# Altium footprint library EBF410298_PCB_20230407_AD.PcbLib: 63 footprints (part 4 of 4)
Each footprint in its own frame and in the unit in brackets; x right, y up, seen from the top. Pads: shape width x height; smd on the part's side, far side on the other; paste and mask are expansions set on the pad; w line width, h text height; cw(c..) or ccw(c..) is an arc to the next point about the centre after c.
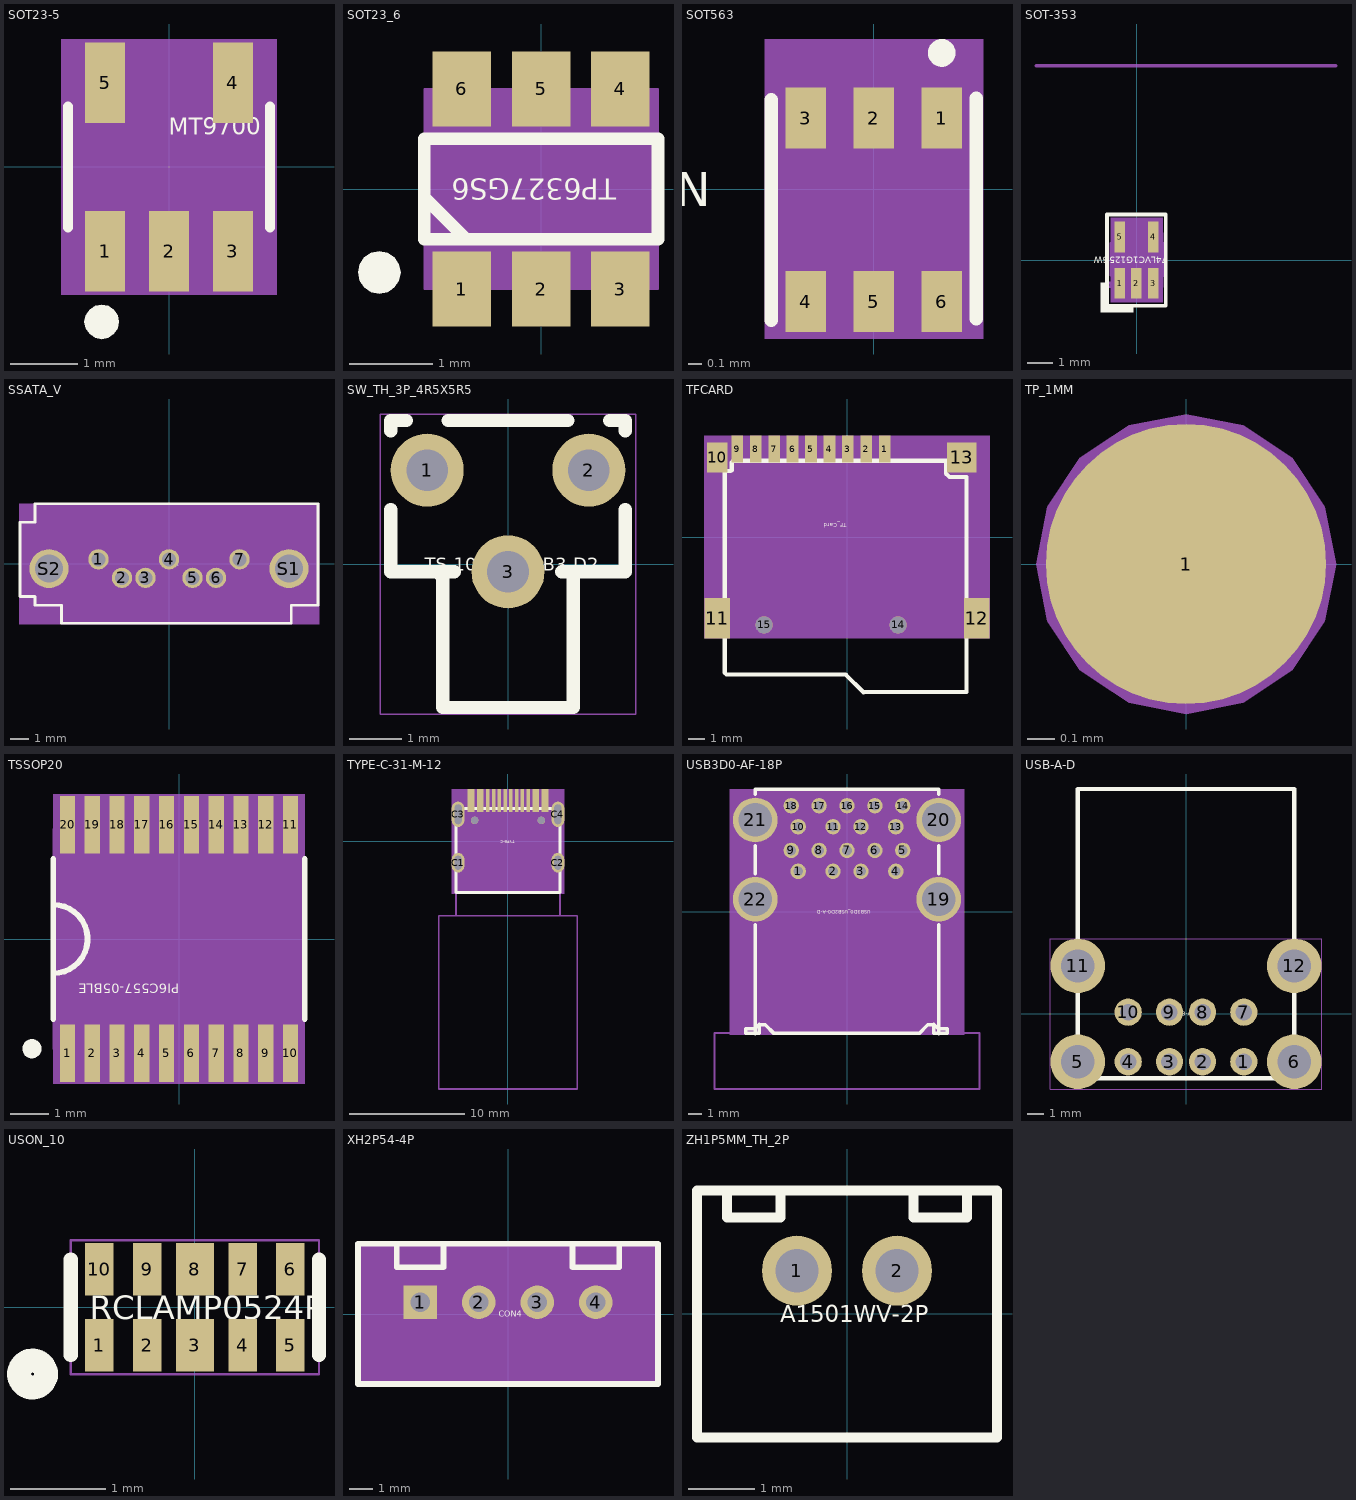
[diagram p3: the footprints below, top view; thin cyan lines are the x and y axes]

## SOT23-5 [mm] "SOT23-5"
pads (5):
  rect 0.599x1.199 smd: 1(-0.95,-1.25) 2(0,-1.25) 3(0.95,-1.25) 4(0.95,1.25) 5(-0.95,1.25)
Top Overlay:
  dashed: -1,-2.555 -0.902,-2.535 -0.82,-2.48 -0.765,-2.398 -0.745,-2.3 -0.765,-2.202 -0.783,-2.175 -0.82,-2.12 -0.902,-2.065 -1,-2.045 -1.098,-2.065 -1.18,-2.12 -1.217,-2.175 -1.235,-2.202 -1.255,-2.3 -1.235,-2.398 -1.18,-2.48 -1.098,-2.535
  lines w0.15: -1.5,-0.9 -1.5,0.9 ; 1.5,-0.9 1.5,0.9
  text "MT9700" at 0,0.475 h0.25
Top 3D Body:
  region: -1.6,1.9 -1.6,-1.9 1.6,-1.9 1.6,1.9
Mechanical 17:
  text "2" at 0,-1.21 h0.1
  text "1" at -0.95,-1.21 h0.1
  text "3" at 0.95,-1.21 h0.1
  text "4" at 0.95,1.29 h0.1
  text "5" at -0.95,1.29 h0.1
Top Assembly:
  lines w0.15: -1.5,-0.85 1.5,-0.85 1.5,0.85 -1.5,0.85 -1.5,-0.85
3D body: height 3.81, standoff 0, extent -1.6,-1.9 1.6,1.9

## SOT23_6 [mm] "SOT23_6"
pads (6):
  rect 0.7x0.9 smd: 1(-0.95,-1.2) 2(0,-1.2) 3(0.95,-1.2) 4(0.95,1.2) 5(0,1.2) 6(-0.95,1.2)
Top Overlay:
  dashed: -2.195,-1 -2.176,-1.098 -2.12,-1.18 -2.038,-1.236 -1.94,-1.255 -1.842,-1.236 -1.815,-1.217 -1.76,-1.18 -1.704,-1.098 -1.685,-1 -1.704,-0.902 -1.76,-0.82 -1.815,-0.783 -1.842,-0.764 -1.94,-0.745 -2.038,-0.764 -2.12,-0.82 -2.176,-0.902
  lines w0.15: -1.4,-0.1 -0.9,-0.6 ; -1.4,-0.6 -1.4,0.6 1.4,0.6 1.4,-0.6 -1.4,-0.6
  text "TP6327GS6" at 0.9,0.125 h0.25
Top 3D Body:
  region: -1.4,-1.2 1.4,-1.2 1.4,1.2 -1.4,1.2
Mechanical 17:
  text "1" at -0.696,-1.2 h0.64
  text "5" at 0.254,1.2 h0.64
  text "4" at 1.204,1.2 h0.64
  text "2" at 0.254,-1.2 h0.64
  text "6" at -0.696,1.2 h0.64
  text "3" at 1.204,-1.2 h0.64
Top Assembly:
  lines w0.025: -1.4,-1.2 1.4,-1.2 1.4,1.2 -1.4,1.2 -1.4,-1.2
3D body: height 3.81, standoff 0, extent -1.4,-1.2 1.4,1.2

## SOT563 [mm] "SOT563"
pads (6):
  rect 0.3x0.45 smd: 1(0.499,0.521) 2(-0.001,0.521) 3(-0.501,0.521) 4(-0.501,-0.829) 5(-0.001,-0.829) 6(0.499,-0.829)
Top Overlay:
  circle w0.1: c0.499,1.001 r0.052
  lines w0.1: -0.754,-0.966 -0.754,0.657 ; 0.754,-0.955 0.754,0.668
  text "NUP5120X6T1G" at -1.2,0.125 h0.25
Top 3D Body:
  region: 0.804,1.104 0.804,-1.104 -0.804,-1.104 -0.804,1.104
Mechanical 17:
  text "2" at -0.245,0.521 h0.3
  text "4" at -0.745,-0.829 h0.3
  text "6" at 0.255,-0.829 h0.3
  text "5" at -0.245,-0.829 h0.3
  text "1" at 0.255,0.521 h0.3
  text "3" at -0.745,0.521 h0.3
3D body: height 3.81, standoff 0, extent -0.804,-1.104 0.804,1.104

## SOT-353 [mil] "SOT-353"
pads (5):
  rect 16x47 smd: 1(-25.91,-35.43) 2(-0.32,-35.43) 3(25.28,-35.43) 4(25.28,35.43) 5(-25.91,35.43)
Top Overlay:
  dashed: -45.31,-35 -55.31,-35 -55.31,-80 -5.32,-80 -5.32,-70 -45.31,-70
  lines w6: -45.31,-70 44.69,-70 44.69,70 -45.31,70 -45.31,-70
  text "74LVC1G125GW" at 47.23,4.92 h9.84
Mechanical 5:
  dashed: -39.69,-65 39.69,-65 39.69,65 -39.69,65
Top 3D Body:
  region: -39.69,-65 39.69,-65 39.69,65 -39.69,65
Top Component Center:
  circle w1: c-0.32,0 r11.81
  circle w1: c-0.32,0 r11.81
  lines w1: -16.06,0 15.43,0 -16.06,0 ; -0.32,-15.75 -0.32,15.75 -0.32,-15.75
Mechanical 17:
  text "5" at -19.11,35.43 h17
  text "1" at -19.11,-35.43 h17
  text "3" at 32.08,-35.43 h17
  text "4" at 32.08,35.43 h17
  text "2" at 6.49,-35.43 h17
Top Assembly:
  circle w3.94: c-41.31,-38 r2.83
  lines w3.94: -32.31,-24 -32.31,-40.83 -20.32,-40.83 ; -31.5,26 -31.5,40.83 ; -31.5,41.83 -19.5,41.83 -19.5,26 ; -20.32,-40 -20.32,-25 ; -6.32,-24 -6.32,-40.83 5.68,-40.83 ; 5.68,-40 5.68,-24 ; 19.68,-24 19.68,-40.83 31.68,-40.83 ; 19.68,26 19.68,41 ; 19.68,41.83 31.68,41.83 31.68,26 ; 31.68,-40 31.68,-24 ; -39.31,-23.61 40.69,-23.61 40.69,25.61 -39.31,25.61 -39.31,-23.61
  text ".Designator" at 58.69,-21 h40
Mechanical 20:
  lines w5: -154.31,298 305.69,298
  text "Remark: ***" at -124.31,98 h25
  text "Rev   : A1" at -124.31,138 h25
  text "Date  : 2007-11-30" at -124.31,178 h25
  text "Creat : Yuki" at -124.31,218 h25
  text "Ref PN: ESDALC6V1W5" at -124.31,258 h25
  text "Sofer Lib Information" at -154.31,308 h25
Mechanical 22:
  lines w1: -39.31,-41 40.69,-41 40.69,42 -39.31,42 -39.31,-41
Mechanical 23:
  text "Approved" at 111.69,0 h35
Mechanical 24:
  text "SOT-353" at 88.69,-163 h30
3D body: height 150, standoff 0, extent -39.69,-65 39.69,65

## SSATA_V [mm] "SSATA_V"
pads (9):
  round 1.1 hole 0.75: 1(-3.81,0.25) 2(-2.54,-0.75) 3(-1.27,-0.75) 4(0,0.25) 5(1.27,-0.75) 6(2.54,-0.75) 7(3.81,0.25)
  round 2.1 hole 1.5: S1(6.48,-0.25) S2(-6.48,-0.25)
Top Overlay:
  lines w0.15: -8.04,-1.75 -7.24,-1.75 -7.24,-2.23 -5.8,-2.23 -5.8,-3.2 6.6,-3.2 6.6,-2.23 8.04,-2.23 8.04,3.25 -7.24,3.25 -7.24,2.25 -8.04,2.25 -8.04,-1.75
  text "SATA" at -0.4,-0.125 h0.25
Top 3D Body:
  region: -8.1,3.25 -8.1,-3.25 8.1,-3.25 8.1,3.25
Mechanical 17:
  text "S2" at -6.8,-0.45 h0.64
  text "S1" at 6.3,-0.45 h0.64
  text "1" at -4.318,0.25 h0.64
  text "4" at -0.508,0.25 h0.64
  text "7" at 3.302,0.25 h0.64
  text "6" at 2.032,-0.75 h0.64
  text "5" at 0.762,-0.75 h0.64
  text "3" at -1.778,-0.75 h0.64
  text "2" at -3.048,-0.75 h0.64
3D body: height 3.81, standoff 0, extent -8.1,-3.25 8.1,3.25

## SW_TH_3P_4R5X5R5 [mm] "SW_TH_3P_4R5X5R5"
pads (3):
  round 1.4 hole 0.8: 1(-1.55,1.8) 2(1.55,1.8) 3(0,-0.15)
Top Overlay:
  lines w0.254: -2.25,1.044 -2.25,-0.15 -1.031,-0.15 ; -2.25,2.556 -2.25,2.75 -1.947,2.75 ; -1.359,-0.15 -1.25,-0.259 -1.25,-2.75 1.25,-2.75 1.25,-0.15 ; -1.153,2.75 1.153,2.75 ; 1.031,-0.15 2.25,-0.15 2.25,1.044 ; 1.947,2.75 2.25,2.75 2.25,2.556
  text "TS-1091B-A5B3-D2" at -1.599,-0.125 h0.25
Top 3D Body:
  lines w0.025: -2.452,-2.877 2.452,-2.877 2.452,2.877 -2.452,2.877 -2.452,-2.877
Mechanical 17:
  text "2" at 1.296,1.8 h0.64
  text "1" at -1.804,1.8 h0.64
  text "3" at -0.254,-0.15 h0.64

## TFCARD [mil] "TFCARD"
pads (15):
  rect 27.56x62.99 smd: 1(88.58,206.82) 2(45.27,206.82) 3(1.97,206.82) 4(-41.34,206.82) 5(-84.65,206.82) 6(-127.95,206.82) 7(-171.26,206.82) 8(-214.57,206.82) 9(-257.88,206.82)
  rect 47.24x70 smd: 10(-305.12,187.13)
  rect 60x95 smd: 11(-305.12,-190.82) 12(305.12,-190.82)
  rect 70x70 smd: 13(269.68,187.13)
  round 40 hole 40 unplated: 14(120.08,-206.57) 15(-194.88,-206.57)
Top Overlay:
  lines w10: -289.12,155.18 -273.12,155.18 -271.12,157.18 -271.12,175.18 -267.12,179.18 232.88,179.18 232.88,149.18 240.88,141.18 280.88,141.18 280.88,-364.05 38.88,-364.82 -3.12,-322.82 -283.12,-322.82 -287.12,-318.82 -287.12,153.18 -289.12,155.18
  text "TF_Card" at -0.01,32.47 h9.84
Top 3D Body:
  region: -335.12,-238.31 -335.12,238.31 335.12,238.31 335.12,-238.31
Mechanical 17:
  text "14" at 120.08,-181.37 h31.5
  text "15" at -194.88,-181.37 h31.5
  text "4" at -41.34,219.42 h31.5
  text "2" at 45.27,219.42 h31.5
  text "9" at -257.88,219.42 h31.5
  text "3" at 1.97,219.42 h31.5
  text "8" at -214.57,219.42 h31.5
  text "7" at -171.26,219.42 h31.5
  text "5" at -84.65,219.42 h31.5
  text "1" at 88.58,219.42 h31.5
  text "12" at 305.12,-165.62 h31.5
  text "11" at -305.12,-165.62 h31.5
  text "13" at 269.68,212.33 h31.5
  text "10" at -305.12,212.33 h31.5
  text "6" at -127.95,219.42 h31.5
3D body: height 150, standoff 0, extent -335.12,-238.31 335.12,238.31

## TP_1MM [mil] "TP_1MM"
pads (1):
  round 40 smd: 1(0,0)
Top 3D Body:
  region: 21.41,0 19.78,8.19 15.14,15.14 8.19,19.78 0,21.41 -8.19,19.78 -10.52,18.23 -15.14,15.14 -19.78,8.19 -21.41,0 -19.78,-8.19 -15.14,-15.14 -10.52,-18.23 -8.19,-19.78 0,-21.41 8.19,-19.78 15.14,-15.14 19.78,-8.19
Mechanical 17:
  text "1" at -11,-11 h25
Top Assembly:
  dashed: 21.41,0 19.78,8.19 15.14,15.14 8.19,19.78 0,21.41 -8.19,19.78 -10.52,18.23 -15.14,15.14 -19.78,8.19 -21.41,0 -19.78,-8.19 -15.14,-15.14 -10.52,-18.23 -8.19,-19.78 0,-21.41 8.19,-19.78 15.14,-15.14 19.78,-8.19
3D body: height 150, standoff 0, extent -21.41,-21.41 21.41,21.41

## TSSOP20 [mm] "TSSOP20"
pads (20):
  rect 0.4x1.5 smd: 1(-2.925,-3) 2(-2.275,-3) 3(-1.625,-3) 4(-0.975,-3) 5(-0.325,-3) 6(0.325,-3) 7(0.975,-3) 8(1.625,-3) 9(2.275,-3) 10(2.925,-3) 11(2.925,3) 12(2.275,3) 13(1.625,3) 14(0.975,3) 15(0.325,3) 16(-0.325,3) 17(-0.975,3) 18(-1.625,3) 19(-2.275,3) 20(-2.925,3)
Top Overlay:
  circle w0.25: c-3.86,-2.88 r0.126
  lines w0.15: -3.3,-2.1 -3.3,2.1 ; -3.3,-0.9 ccw(c-3.3,0) -3.3,0.9 ; 3.3,-2.1 3.3,2.1
  text "PI6C557-05BLE" at 0,-1.175 h0.25
Top 3D Body:
  region: -3.3,-3.8 3.3,-3.8 3.3,3.8 -3.3,3.8
Mechanical 17:
  text "6" at 0.325,-3.203 h0.51
  text "1" at -2.925,-3.203 h0.51
  text "10" at 2.925,-3.406 h0.51
  text "18" at -1.625,2.594 h0.51
  text "8" at 1.625,-3.203 h0.51
  text "19" at -2.275,2.594 h0.51
  text "20" at -2.925,2.594 h0.51
  text "17" at -0.975,2.594 h0.51
  text "2" at -2.275,-3.203 h0.51
  text "7" at 0.975,-3.203 h0.51
  text "3" at -1.625,-3.203 h0.51
  text "9" at 2.275,-3.203 h0.51
  text "16" at -0.325,2.594 h0.51
  text "4" at -0.975,-3.203 h0.51
  text "15" at 0.325,2.594 h0.51
  text "5" at -0.325,-3.203 h0.51
  text "12" at 2.275,2.594 h0.51
  text "11" at 2.925,2.594 h0.51
  text "14" at 0.975,2.594 h0.51
  text "13" at 1.625,2.594 h0.51
Top Assembly:
  lines w0.025: -3.3,-2.9 3.3,-2.9 3.3,2.9 -3.3,2.9 -3.3,-2.9
3D body: height 3.81, standoff 0, extent -3.3,-3.8 3.3,3.8

## TYPE-C-31-M-12 [mm] "TYPE-C-31-M-12"
pads (22):
  rect 0.3x2 smd: A1(-3.35,3.539) A4(-2.55,3.539) A5(-1.25,3.539) A6(-0.249,3.539) A7(0.249,3.539) A8(1.25,3.539) A9(2.55,3.539) A12(3.35,3.539) B1(3.05,3.539) B4(2.25,3.539) B5(1.75,3.539) B6(0.749,3.539) B7(-0.749,3.539) B8(-1.75,3.539) B9(-2.25,3.539) B12(-3.05,3.539)
  oval 1.1x1.7 hole 1.2 slot 0.6 at 0 deg: C1(-4.32,-1.84) C2(4.32,-1.84)
  oval 1.1x2.2 hole 1.7 slot 0.6 at 0 deg: C3(-4.32,2.351) C4(4.32,2.351)
  round 0.65 hole 0.65 unplated: ""(-2.89,1.82) ""(2.89,1.82)
Top Overlay:
  lines w0.249: -4.501,-4.431 4.501,-4.431 4.501,2.861 -4.501,2.861 -4.501,-4.431
  text "TYPE-C" at 0.6,0.125 h0.25
Top 3D Body:
  region: -4.869,-4.54 4.869,-4.54 4.869,4.54 -4.869,4.54
Mechanical 17:
  text "B5" at 2.055,3.539 h0.38
  text "C4" at 4.625,2.351 h0.38
  text "C2" at 4.625,-1.84 h0.38
  text "C1" at -4.016,-1.84 h0.38
  text "C3" at -4.016,2.351 h0.38
  text "B9" at -1.946,3.539 h0.38
  text "A4" at -2.245,3.539 h0.38
  text "B4" at 2.555,3.539 h0.38
  text "A9" at 2.855,3.539 h0.38
  text "A5" at -0.945,3.539 h0.38
  text "B1" at 3.355,3.539 h0.38
  text "A12" at 3.808,3.539 h0.38
  text "A1" at -3.046,3.539 h0.38
  text "B12" at -2.593,3.539 h0.38
  text "A6" at 0.056,3.539 h0.38
  text "B6" at 1.054,3.539 h0.38
  text "A7" at 0.554,3.539 h0.38
  text "B7" at -0.445,3.539 h0.38
  text "B8" at -1.445,3.539 h0.38
  text "A8" at 1.555,3.539 h0.38
Top Assembly:
  lines w0.15: -4.5,-4.44 -4.5,-6.431 ; 0,-6.431 6,-6.431 6,-21.431 -6,-21.431 -6,-6.431 -4.5,-6.431 ; 4.501,-4.431 4.501,-6.431 -4.5,-6.431
3D body: height 3.81, standoff 0, extent -4.869,-4.54 4.869,4.54

## USB3D0-AF-18P [mil] "USB3D0-AF-18P"
pads (22):
  round 43.3 hole 27.6: 1(-137.8,114.15) 2(-39.4,114.15) 3(39.4,114.15) 4(137.8,114.15) 5(157.5,173.25) 6(78.7,173.25) 7(0,173.25) 8(-78.7,173.25) 9(-157.5,173.25) 10(-137.8,240.15) 11(-39.4,240.15) 12(39.4,240.15) 13(137.8,240.15) 14(157.5,299.25) 15(78.7,299.25) 16(0,299.25) 17(-78.7,299.25) 18(-157.5,299.25)
  round 126 hole 94.5: 19(258.7,35.45) 20(258.7,259.05) 21(-258.7,259.05) 22(-258.7,35.45)
Top Overlay:
  lines w10: -258.7,-344.05 -258.7,-36.65 ; -258.7,107.55 -258.7,186.95 ; -258.7,331.15 -258.7,345.45 258.7,345.45 258.7,331.15 ; -247.4,-317.15 -260.5,-330.25 -285.7,-330.25 -285.7,-343.25 -247.4,-343.25 -247.4,-318.55 -230.7,-318.55 -206.1,-343.25 199.5,-343.25 ; 203.5,-343.25 228.2,-318.55 244.8,-318.55 244.8,-343.25 283.2,-343.25 283.2,-330.25 257.9,-330.25 244.8,-317.15 ; 258.7,-344.05 258.7,-36.65 ; 258.7,107.55 258.7,186.95
  text "USB3D0_USB2D0-A-D" at 66.91,4.92 h9.84
Top 3D Body:
  region: -330.7,346.45 -330.7,-346.45 330.7,-346.45 330.7,346.45
Mechanical 17:
  text "13" at 157.8,240.15 h25
  text "16" at 20,299.25 h25
  text "4" at 147.8,114.15 h25
  text "7" at 10,173.25 h25
  text "10" at -117.8,240.15 h25
  text "9" at -147.5,173.25 h25
  text "3" at 49.4,114.15 h25
  text "11" at -19.4,240.15 h25
  text "12" at 59.4,240.15 h25
  text "5" at 167.5,173.25 h25
  text "8" at -68.7,173.25 h25
  text "21" at -238.7,259.05 h25
  text "22" at -238.7,35.45 h25
  text "19" at 278.7,35.45 h25
  text "20" at 278.7,259.05 h25
  text "2" at -29.4,114.15 h25
  text "6" at 88.7,173.25 h25
  text "1" at -127.8,114.15 h25
  text "18" at -137.5,299.25 h25
  text "17" at -58.7,299.25 h25
  text "15" at 98.7,299.25 h25
  text "14" at 177.5,299.25 h25
Top Assembly:
  lines w5.91: -374.02,-499.98 -374.02,-342.5 374.02,-342.5 374.02,-499.98 -374.02,-499.98
3D body: height 150, standoff 0, extent -330.7,-346.45 330.7,346.45

## USB-A-D [mm] "USB-A-D"
pads (12):
  round 1.651 hole 1: 1(3.5,-2.9) 2(1,-2.9) 3(-1,-2.9) 4(-3.5,-2.9) 7(3.5,0.1) 8(1,0.1) 9(-1,0.1) 10(-3.5,0.1)
  round 3.3 hole 2: 5(-6.55,-2.9) 6(6.55,-2.9) 11(-6.55,2.9) 12(6.55,2.9)
Top Overlay:
  lines w0.254: -6.55,-3.9 6.55,-3.9 6.55,13.6 -6.55,13.6 -6.55,-3.9
  text "USB-A-D" at -0.7,-0.125 h0.25
Top 3D Body:
  lines w0.025: -8.2,-4.55 8.2,-4.55 8.2,4.55 -8.2,4.55 -8.2,-4.55
Mechanical 17:
  text "1" at 3.124,-2.9 h0.94
  text "7" at 3.124,0.1 h0.94
  text "4" at -3.876,-2.9 h0.94
  text "10" at -4.252,0.1 h0.94
  text "5" at -6.926,-2.9 h0.94
  text "11" at -7.302,2.9 h0.94
  text "6" at 6.174,-2.9 h0.94
  text "12" at 5.798,2.9 h0.94
  text "8" at 0.624,0.1 h0.94
  text "9" at -1.376,0.1 h0.94
  text "2" at 0.624,-2.9 h0.94
  text "3" at -1.376,-2.9 h0.94

## USON_10 [mm] "USON_10"
pads (10):
  rect 0.3x0.55 smd: 1(-1,-0.4) 2(-0.5,-0.4) 4(0.5,-0.4) 5(1,-0.4) 6(1,0.4) 7(0.5,0.4) 9(-0.5,0.4) 10(-1,0.4)
  rect 0.4x0.55 smd: 3(0,-0.4) 8(0,0.4)
Top Overlay:
  circle w0.25: c-1.7,-0.7 r0.141
  lines w0.15: -1.3,-0.5 -1.3,0.5 ; 1.3,-0.5 1.3,0.5
  text "RCLAMP0524P" at -1.1,-0.125 h0.25
Top 3D Body:
  lines w0.025: -1.3,-0.7 1.3,-0.7 1.3,0.7 -1.3,0.7 -1.3,-0.7
Mechanical 17:
  text "8" at -0.254,0.4 h0.64
  text "3" at -0.254,-0.4 h0.64
  text "6" at 0.746,0.4 h0.64
  text "5" at 0.746,-0.4 h0.64
  text "10" at -1.508,0.4 h0.64
  text "1" at -1.254,-0.4 h0.64
  text "7" at 0.246,0.4 h0.64
  text "4" at 0.246,-0.4 h0.64
  text "9" at -0.754,0.4 h0.64
  text "2" at -0.754,-0.4 h0.64

## XH2P54-4P [mm] "XH2P54-4P"
pads (4):
  rect 1.45x1.45 hole 0.85: 1(-3.81,0.508)
  round 1.45 hole 0.85: 2(-1.27,0.508) 3(1.27,0.508) 4(3.81,0.508)
Top Overlay:
  lines w0.254: -6.51,-3.032 6.51,-3.032 6.51,3.048 -6.51,3.048 -6.51,-3.032 ; -4.826,2.032 -2.794,2.032 -2.794,3.048 -4.826,3.048 -4.826,2.032 ; 2.794,2.032 4.826,2.032 4.826,3.048 2.794,3.048 2.794,2.032
  text "CON4" at -0.4,-0.125 h0.25
Top 3D Body:
  region: -6.477,-3.048 6.477,-3.048 6.477,3.048 -6.477,3.048
Mechanical 17:
  text "2" at -1.524,0.508 h0.64
  text "3" at 1.016,0.508 h0.64
  text "1" at -4.064,0.508 h0.64
  text "4" at 3.556,0.508 h0.64
3D body: height 3.81, standoff 0, extent -6.477,-3.048 6.477,3.048

## ZH1P5MM_TH_2P [mm] "ZH1P5MM_TH_2P"
pads (2):
  round 1.05 hole 0.65: 1(-0.75,0.65) 2(0.75,0.65)
Top Overlay:
  lines w0.15: -1.8,1.85 -1.8,1.45 -1,1.45 -1,1.85 ; 1,1.85 1,1.45 1.8,1.45 1.8,1.85 ; -2.25,-1.85 2.25,-1.85 2.25,1.85 -2.25,1.85 -2.25,-1.85
  text "A1501WV-2P" at -1,-0.125 h0.25
Top 3D Body:
  lines w0.025: -2.2,-1.85 2.2,-1.85 2.2,1.85 -2.2,1.85 -2.2,-1.85
Mechanical 17:
  text "1" at -1.065,0.65 h0.79
  text "2" at 0.435,0.65 h0.79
